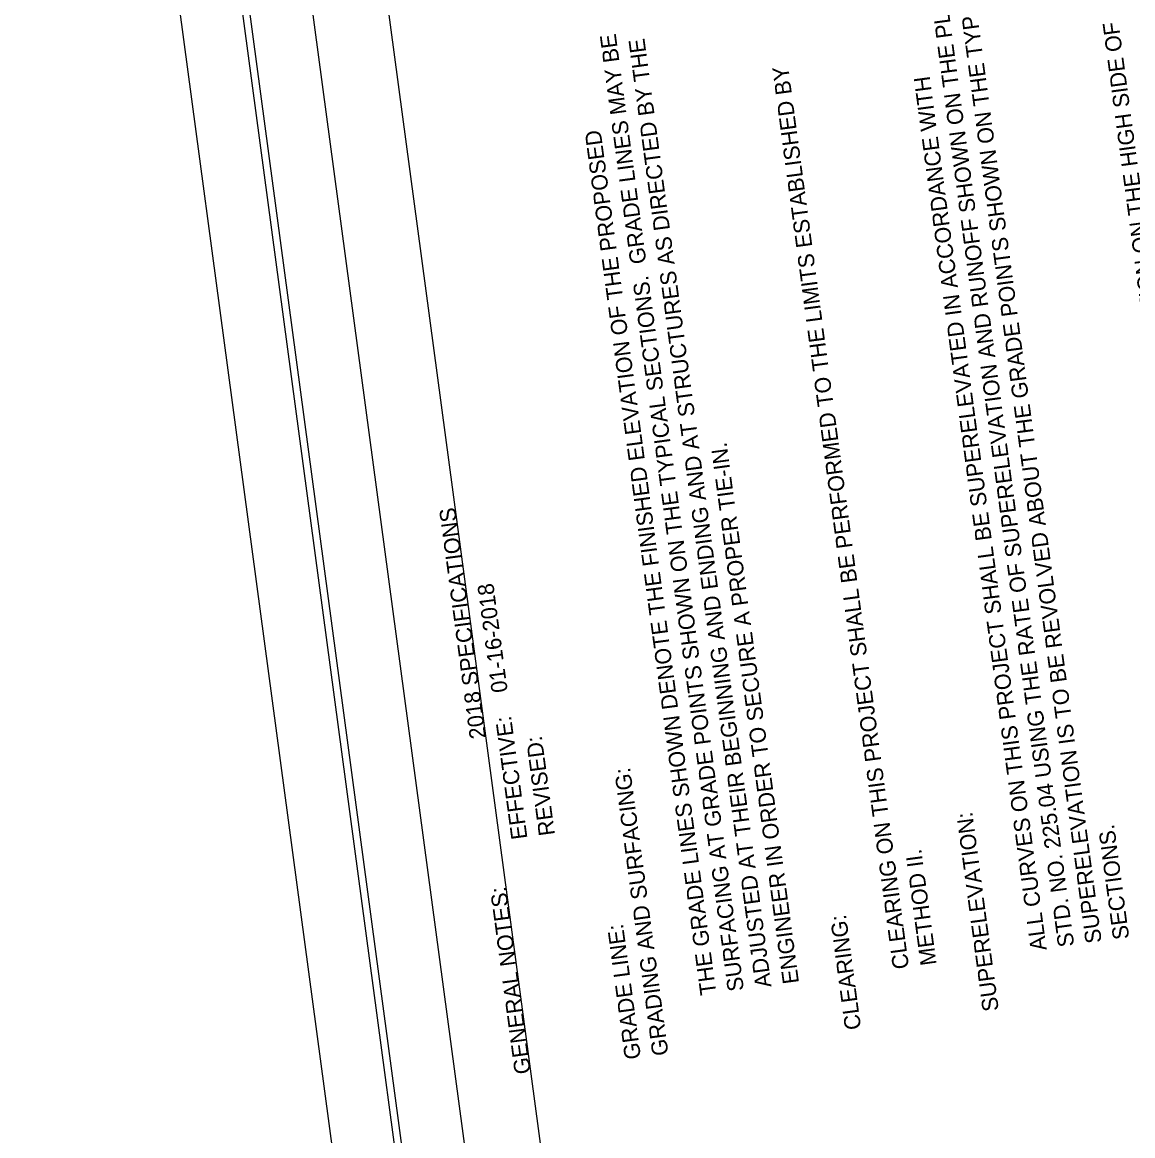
# Model space of a CAD drawing. Extents: x 2573931 to 2578852, y 980053 to 983667.
# Drawn here: x 2573931 to 2574414.5, y 982227.9 to 982712.4 of the extents above; entities that cross this region are included whole.
import ezdxf

# ---------------------------------------------------------------- set-up
doc = ezdxf.new("R2010")
doc.units = 0
for name, color, linetype in [('Scratch_Level_1', 7, 'Continuous'), ('Sheet Border Standard 30in CELL', 7, 'Continuous'), ('Sheet Data Text CELL', 7, 'Continuous'), ('Sheet Plot Border Inside CELL', 7, 'Continuous'), ('Sheet Plot Border Outside CELL', 7, 'Continuous')]:
    doc.layers.add(name, color=color, linetype=linetype)

msp = doc.modelspace()

# ---------------------------------------------------------------- linework, layer by layer
at = {"layer": 'Scratch_Level_1'}
for p, q in [((2574284.78, 981268.49), (2573963.13, 983666.66)), ((2574252.3, 981264.13), (2573930.99, 983659.79))]:
    msp.add_line(p, q, dxfattribs=at)
at = {"layer": 'Sheet Border Standard 30in CELL'}
msp.add_lwpolyline([(2573998.57, 982950.72), (2574237.85, 981166.7), (2575486.67, 981334.19), (2575247.39, 983118.21)], close=True, dxfattribs=at)
at = {"layer": 'Sheet Plot Border Inside CELL'}
msp.add_lwpolyline([(2573993.55, 982965.18), (2574259.38, 980983.13), (2575514.27, 981151.44), (2575248.43, 983133.49)], close=True, dxfattribs=at)
at = {"layer": 'Sheet Plot Border Outside CELL'}
msp.add_lwpolyline([(2573966.13, 982966.95), (2574234.76, 980964.09), (2575543.04, 981139.56), (2575274.41, 983142.42)], close=True, dxfattribs=at)

# ---------------------------------------------------------------- texts
at = {"layer": 'Sheet Data Text CELL'}
for s, p in [('         STD. NO. 225.04 USING THE RATE OF SUPERELEVATION AND RUNOFF SHOWN ON THE PLANS.', (2574392.12, 982287.25)), ('         SUPERELEVATION IS TO BE REVOLVED ABOUT THE GRADE POINTS SHOWN ON THE TYPICAL ', (2574404.11, 982288.86)), ('         ASPHALT, EARTH, AND CONCRETE SHOULDER CONSTRUCTION ON THE HIGH SIDE OF', (2574464.03, 982296.9)), ('         SURFACING AT GRADE POINTS SHOWN ON THE TYPICAL SECTIONS.  GRADE LINES MAY BE ', (2574248.32, 982267.97)), ('         ADJUSTED AT THEIR BEGINNING AND ENDING AND AT STRUCTURES AS DIRECTED BY THE ', (2574260.3, 982269.57)), ('         CLEARING ON THIS PROJECT SHALL BE PERFORMED TO THE LIMITS ESTABLISHED BY ', (2574320.22, 982277.61)), ('         ALL CURVES ON THIS PROJECT SHALL BE SUPERELEVATED IN ACCORDANCE WITH', (2574380.14, 982285.64)), ('         THE GRADE LINES SHOWN DENOTE THE FINISHED ELEVATION OF THE PROPOSED ', (2574236.34, 982266.36)), ('         ENGINEER IN ORDER TO SECURE A PROPER TIE-IN.  ', (2574272.29, 982271.18)), ('GENERAL NOTES:                         2018 SPECIFICATIONS', (2574152.45, 982255.11)), ('                                       EFFECTIVE:    01-16-2018', (2574164.44, 982256.71)), ('                                       REVISED:      ', (2574176.42, 982258.32)), ('GRADING AND SURFACING:  ', (2574212.37, 982263.14)), ('SUPERELEVATION:  ', (2574356.17, 982282.43)), ('         SECTIONS.  ', (2574416.09, 982290.47)), ('         METHOD II.', (2574332.21, 982279.22)), ('CLEARING:  ', (2574296.25, 982274.39)), ('GRADE LINE:  ', (2574200.39, 982261.54))]:
    msp.add_text(s, height=7, rotation=97.639, dxfattribs=at).set_placement(p)

doc.saveas('drawing.dxf')
